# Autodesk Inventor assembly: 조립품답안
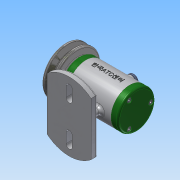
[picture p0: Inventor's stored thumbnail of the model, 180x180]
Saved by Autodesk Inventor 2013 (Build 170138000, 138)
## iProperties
Created: 2017-12
Part Number: 조립품답안
Document SubType Name: Assembly
Designer: Administrator
Author: Administrator
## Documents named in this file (14)
- C:\Users\Administrator\Desktop\471208V1013\조립품답안.iam
- C:\Users\Administrator\Desktop\471208V1013\본체.ipt
- C:\Users\Administrator\Desktop\471208V1013\V벨트풀리.ipt
- C:\Users\Administrator\Desktop\471208V1013\고무캡.ipt
- C:\Users\Administrator\Desktop\471208V1013\너트 M 8.ipt
- C:\Users\Administrator\Desktop\471208V1013\뒤커버.ipt
- C:\Users\Administrator\Desktop\471208V1013\베어링 15 x 32 x 9.ipt
- C:\Users\Administrator\Desktop\471208V1013\볼트 M4 x 12.ipt
- C:\Users\Administrator\Desktop\471208V1013\스프링와셔 8.ipt
- C:\Users\Administrator\Desktop\471208V1013\앞커버.ipt
- C:\Users\Administrator\Desktop\471208V1013\오일 실 15 25 7.ipt
- C:\Users\Administrator\Desktop\471208V1013\와셔 8x17.ipt
- C:\Users\Administrator\Desktop\471208V1013\축.ipt
- C:\Users\Administrator\Desktop\471208V1013\키 3 x 3 x 12.ipt
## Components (2 placed, 2 different names)
1. V벨트풀리:1 — 각도:2
2. 고무캡:1
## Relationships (1: Angle 1)
- 각도:2 [Angle]: V벨트풀리:1
